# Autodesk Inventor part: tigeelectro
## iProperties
Created: 2007-07
Part Number: tigeelectro
Document SubType Name: Modeling
Designer: EF
Density: 1 g/cm^3
Author: EF
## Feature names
1. Base1
2. Extrusion1
3. Extrusion2
4. Extrusion3
5. Extrusion4
6. Extrusion5
